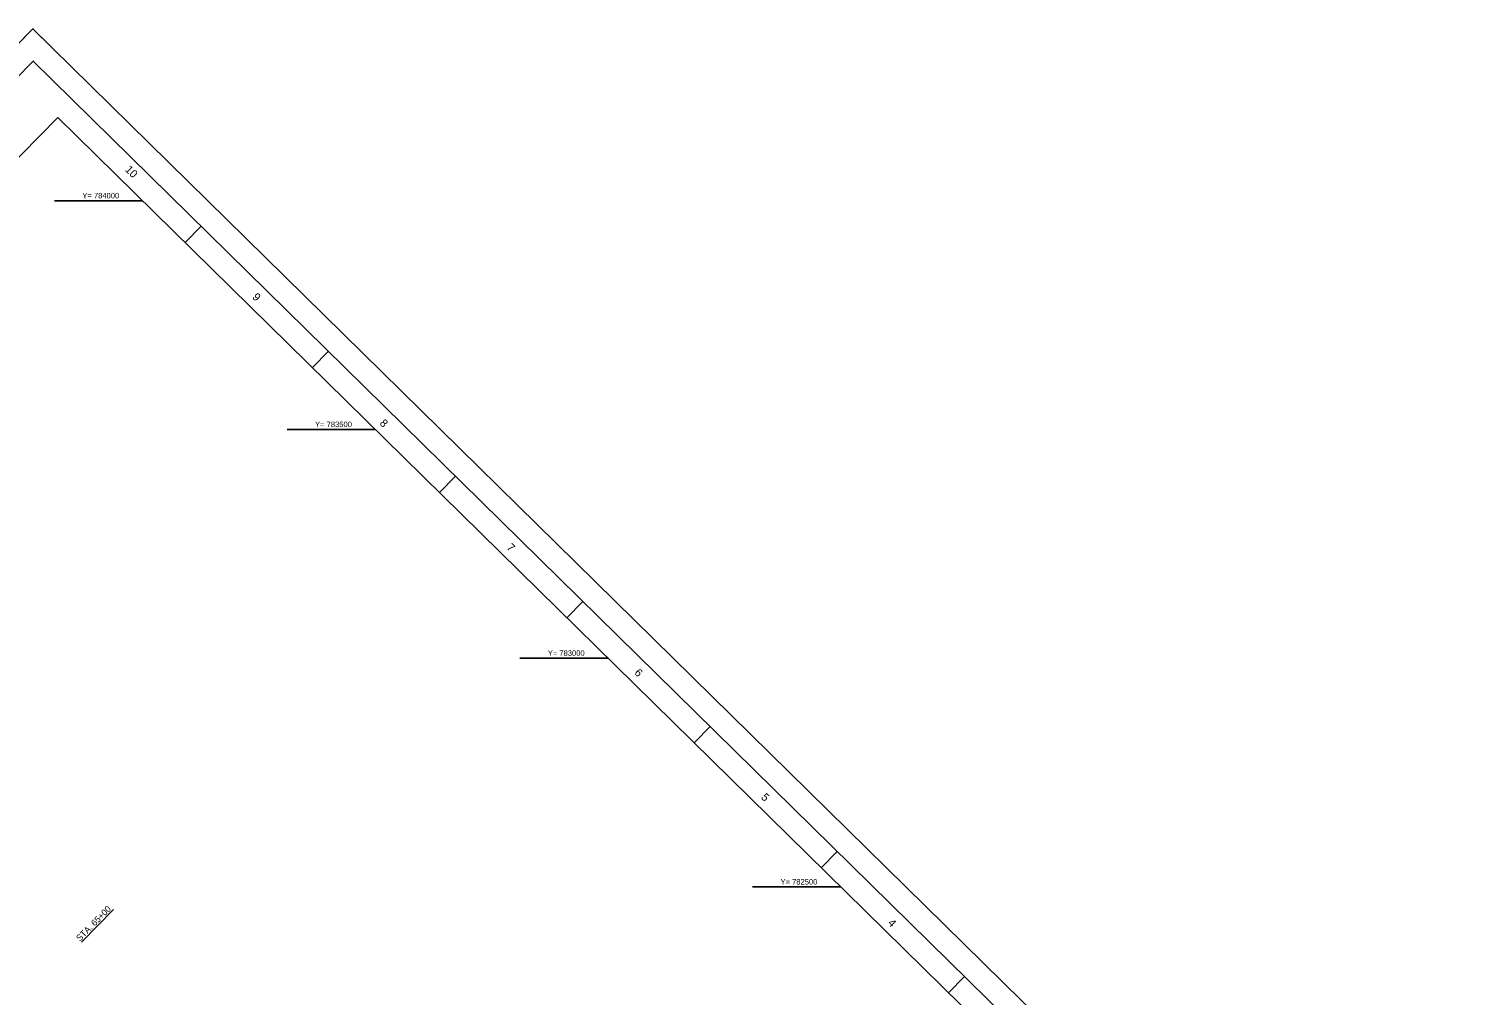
# Model space of a CAD drawing. Extents: x 614899 to 620420, y 778867 to 784376.
# Drawn here: x 617273 to 620420, y 782263 to 784376 of the extents above; entities that cross this region are included whole.
import ezdxf

# ---------------------------------------------------------------- set-up
doc = ezdxf.new("R2010")
doc.units = 0
for name, color, linetype in [('G-ANNO-NPLT', 7, 'Continuous'), ('G-ANNO-TTLB', 7, 'Continuous'), ('V-ALGN-TEXT', 7, 'Continuous'), ('V-TOPO-COOR-STAT', 7, 'Continuous')]:
    doc.layers.add(name, color=color, linetype=linetype)

msp = doc.modelspace()

# ---------------------------------------------------------------- linework, layer by layer
at = {"layer": 'G-ANNO-NPLT'}
msp.add_lwpolyline([(617282, 784375.7), (620420.5, 781292), (618037.6, 778866.8), (614899.1, 781950.5)], close=True, dxfattribs=at)
msp.add_lwpolyline([(617247, 784340.1), (617282, 784375.7), (617317.7, 784340.7)], dxfattribs=at)
at = {"layer": 'G-ANNO-TTLB'}
for p, q in [((617650, 783944.1), (617614.9, 783908.4)), ((617928.2, 783670.8), (617893.1, 783635.1)), ((617928.2, 783670.8), (617893.1, 783635.1)), ((618206.3, 783397.4), (618171.3, 783361.8)), ((618484.5, 783124.1), (618449.5, 783088.4)), ((618762.7, 782850.7), (618727.7, 782815.1)), ((619040.9, 782577.4), (619005.9, 782541.7)), ((619319.1, 782304.1), (619284, 782268.4))]:
    msp.add_line(p, q, dxfattribs=at)
for points in [[(614969.8, 781951.2), (618036.9, 778937.5), (620349.8, 781291.3), (617282.6, 784305)], [(620279.1, 781290.7), (617336.7, 784181.8), (615094, 781899.2), (618036.3, 779008.2)]]:
    msp.add_lwpolyline(points, close=True, dxfattribs=at)
at = {"layer": 'V-ALGN-TEXT'}
msp.add_line((617387.9, 782379.1), (617458, 782450.4), dxfattribs=at)
at = {"layer": 'V-TOPO-COOR-STAT'}
for p, q in [((617329.1, 784000), (617521.7, 784000)), ((617838, 783500), (618030.6, 783500)), ((618346.8, 783000), (618539.5, 783000)), ((618855.7, 782500), (619048.3, 782500))]:
    msp.add_line(p, q, dxfattribs=at)

# ---------------------------------------------------------------- texts
at = {"layer": 'G-ANNO-TTLB'}
for s, p in [('10', (617482, 784066.3)), ('9', (617760.5, 783787.8)), ('8', (618038.8, 783512)), ('7', (618316.5, 783240.1)), ('6', (618595.9, 782966.6)), ('5', (618872.9, 782694.3)), ('4', (619150.1, 782419.4))]:
    msp.add_text(s, height=17.5, rotation=315.5037, dxfattribs=at).set_placement(p)
at = {"layer": 'V-ALGN-TEXT'}
msp.add_text('STA. 65+00', height=13.92, rotation=45.5037, dxfattribs=at).set_placement((617384.8, 782379.8))
at = {"layer": 'V-TOPO-COOR-STAT'}
for s, p in [('Y= 784000', (617390, 784005)), ('Y= 783500', (617898.9, 783505)), ('Y= 783000', (618407.8, 783005)), ('Y= 782500', (618916.7, 782505))]:
    msp.add_text(s, height=12, dxfattribs=at).set_placement(p)

doc.saveas('drawing.dxf')
